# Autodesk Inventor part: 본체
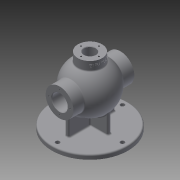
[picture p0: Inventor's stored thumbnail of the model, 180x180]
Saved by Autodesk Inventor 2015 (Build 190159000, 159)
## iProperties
Created: 2020-08
Part Number: 본체
Material: 일반
Document SubType Name: Modeling
Designer: now
Density: 1 g/cm^3
Appearance: 기본값
Author: now
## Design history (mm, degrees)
sketch "스케치1"
  geometry: C1 r 85 at (0, 0); 1 further point
  constraints: 1 centre point, 1 coincident
  dimensions: "d0" = 170 diameter of C1
extrude "돌출1" new body sketch "스케치1" distance "d1" = 10; taper "d2" = 0 deg
sketch "스케치2"
  geometry: L1 (4, 52)-(-4, 52); L2 (-4, 52)-(-4, -52); L3 (-4, -52)-(4, -52); L4 (4, -52)-(4, 52); L5 (4, 52)-(-4, -52); L6 (-4, 52)-(4, -52); C1 r 85 at (0, 0) reference
  constraints: 12 end point, 2 midpoint, 2 parallel, 1 horizontal, 1 perpendicular
  dimensions: "d3" = 104 distance of L3.end L1.start; "d4" = 8 distance of L2.end L3.end
extrude "돌출2" join sketch "스케치2" distance "d5" = 75; taper "d6" = 0 deg
sketch "스케치3"
  geometry: L1 (43, 4)-(-43, 4); L2 (-43, 4)-(-43, -4); L3 (-43, -4)-(43, -4); L4 (43, -4)-(43, 4); L5 (43, 4)-(-43, -4); L6 (-43, 4)-(43, -4); C1 r 85 at (0, 0) reference
  constraints: 12 end point, 2 midpoint, 2 parallel, 1 horizontal, 1 perpendicular
  dimensions: "d7" = 8 distance of L1.end L2.end; "d8" = 86 distance of L2.end L3.end
extrude "돌출3" join sketch "스케치3" distance "d9" = 75; taper "d10" = 0 deg
sketch "스케치4"
  geometry: L1 (85, 10)-(85, 0) reference; L2 (85, 0)-(-85, 0) reference; L3 (-85, 0)-(-85, 10) reference; L4 (-85, 10)-(-52, 10) reference; L5 (-52, 10)-(-52, 85) reference; L6 (-52, 85)-(52, 85) reference; L7 (52, 85)-(52, 10) reference; L8 (52, 10)-(85, 10) reference; L9 (68, 116)-(68, 85); L10 (68, 85)-(-68, 85); L11 (-68, 85)-(-68, 116); L12 (-68, 116)-(-42.988, 116); L13 (42.988, 116)-(68, 116); A1 r 53 centre (0, 85) between (42.988, 116) and (-42.988, 116); 2 further points
  constraints: 10 end point, 3 parallel, 2 horizontal, 2 midpoint, 2 perpendicular, 2 point on circle, 1 centre point, 1 vertical alignment
  dimensions: "d12" = 31 distance of L10.end L11.end; "d13" = 53 radius of A1; "d14" = 136 distance of L11.end L9.start; "d17" = 85 distance of point (0, 0) A1.centre; "d18" = 31 distance between parallel lines of L10 L13
revolve "회전1" sketch "스케치4" stored, may be unused: angle "d19" = 90 deg
node "작업 평면1"
sketch "스케치5"
  geometry: C1 r 27 at (0, 0); 1 further point
  constraints: 1 centre point, 1 coincident
  dimensions: "d21" = 54 diameter of C1
extrude "돌출4" join sketch "스케치5" stored distance "d22" = 75; taper "d23" = 0 deg
sketch "스케치6"
  geometry: L1 (68, 54)-(52, 54) reference; L2 (52, 54)-(52, 10) reference; L3 (52, 10)-(85, 10) reference; L4 (85, 10)-(85, 0) reference; L5 (85, 0)-(-85, 0) reference; L6 (-85, 0)-(-85, 10) reference; L7 (-85, 10)-(-52, 10) reference; L8 (-52, 10)-(-52, 54) reference; L9 (-52, 54)-(-68, 54) reference; L10 (-68, 54)-(-68, 116) reference; L11 (-68, 116)-(-42.988, 116) reference; L12 (-27, 130.607)-(-27, 150) reference; L13 (-27, 150)-(27, 150) reference; L14 (27, 150)-(27, 130.607) reference; L15 (42.988, 116)-(68, 116) reference; L16 (68, 116)-(68, 54) reference; L17 (-68, 54)-(-68, 116) reference; L18 (-68, 85)-(68, 85); L19 (68, 54)-(68, 116) reference; L20 (-43, 85)-(43, 85); L21 (42.988, 54.259)-(42.988, 116) reference; A1 r 53 centre (0, 85) between (-27, 130.607) and (-42.988, 116) reference; A2 r 53 centre (0, 85) between (42.988, 116) and (27, 130.607) reference; A3 r 43 centre (0, 85) between (43, 85) and (-43, 85); 1 further point
  constraints: 4 end point, 2 midpoint, 2 point on circle, 2 point on line, 1 centre point, 1 coincident, 1 perpendicular
  dimensions: "d25" = 43 radius of A3
revolve "회전2" sketch "스케치6" stored, may be unused: angle "d26" = 90 deg
sketch "스케치7"
  geometry: C1 r 31 at (0, 0) reference; C2 r 17.5 at (0, 0); 1 further point
  constraints: 1 centre point, 1 coincident
  dimensions: "d27" = 35 diameter of C2
extrude "돌출5" cut sketch "스케치7" distance "d28" = 16; taper "d29" = 0 deg
sketch "스케치9"
  geometry: C1 r 31 at (0, 0) reference; 1 further point
hole "구멍1" sketch "스케치9" at (0, 0) diameter "d33" = 35; stored, may be unused: countersink angle "d37" = 90 deg, drill point angle "d39" = 118 deg; dims "d34" = 6, "d35" = 4, "d36" = 2, "d38" = 8
sketch "스케치10"
  geometry: C1 r 27 at (0, 0) reference; C2 r 13 at (0, 0)
  constraints: 1 centre point, 1 coincident
  dimensions: "d40" = 26 diameter of C2
extrude "돌출7" cut sketch "스케치10" stored distance "d41" = 1.75; taper "d42" = 0 deg
sketch "스케치11"
  geometry: C1 r 17.5 at (0, 0) reference; 2 further points
  constraints: 1 vertical alignment
  dimensions: "d43" = 24 distance of C1.centre point (0, 24)
hole "구멍2" sketch "스케치11" at (0, 24) diameter "d44" = 3.242; stored, may be unused: countersink angle "d48" = 90 deg, drill point angle "d50" = 118 deg; dims "d45" = 12, "d46" = 4, "d47" = 2, "d49" = 15
sketch "스케치12"
  geometry: C1 r 13 at (0, 0) reference; 1 further point
  constraints: 1 horizontal alignment
  dimensions: "d54" = 20 distance of C1.centre point (-20, 0)
hole "구멍3" sketch "스케치12" at (-20, 0) diameter "d55" = 3.242; stored, may be unused: countersink angle "d59" = 90 deg, drill point angle "d61" = 118 deg; dims "d56" = 12, "d57" = 4, "d58" = 2, "d60" = 15
sketch "스케치13"
  geometry: C1 r 85 at (0, 0) reference; A1 r 72.5 centre (0, 0) between (-72.5, 0) and (0, 72.5); 2 further points
  constraints: 4 point on circle, 2 horizontal alignment, 2 vertical alignment, 1 centre point, 1 coincident
  dimensions: "d65" = 145 diameter of A1
hole "구멍4" sketch "스케치13" at (-72.5, 0), (0, 72.5), (0, -72.5), (72.5, 0) diameter "d66" = 9; stored, may be unused: countersink angle "d70" = 90 deg, drill point angle "d72" = 118 deg; dims "d67" = 12, "d68" = 4, "d69" = 2, "d71" = 15
chamfer "모따기1" distance "d73" = 1; stored, may be unused: second distance "d74" = 2, angle "d75" = 45 deg
chamfer "모따기2" distance "d76" = 1; stored, may be unused: second distance "d77" = 2, angle "d78" = 45 deg
chamfer "모따기3" distance "d79" = 1; stored, may be unused: second distance "d80" = 2, angle "d81" = 45 deg
fillet "모깎기1" dims "d82" = 3
fillet "모깎기2" dims "d83" = 3
fillet "모깎기3" dims "d84" = 3
fillet "모깎기4" dims "d85" = 3
fillet "모깎기5" dims "d86" = 3
fillet "모깎기6" dims "d87" = 3
node "작업 평면2"
sketch "스케치14"
  geometry: L1 (68, 100.232)-(68, 69.768) reference; L2 (68, 69.768)-(44.497, 69.768) reference; L3 (4, 36.441)-(4, 13) reference; L4 (7, 10)-(77.427, 10) reference; L5 (80.598, 7)-(80.598, 0) reference; L6 (80.598, 0)-(-80.598, 0) reference; L7 (-80.598, 0)-(-80.598, 7) reference; L8 (-77.427, 10)-(-7, 10) reference; L9 (-4, 13)-(-4, 36.441) reference; L10 (-44.497, 69.768)-(-68, 69.768) reference; L11 (-68, 69.768)-(-68, 100.232) reference; L12 (-68, 100.232)-(-44.497, 100.232) reference; L13 (44.497, 100.232)-(68, 100.232) reference; L14 (0, 150)-(0, 132.286) reference; L15 (27, 150)-(-27, 150) reference; L16 (27, 150)-(-27, 150) reference; L17 (-27, 132.286)-(27, 132.286) reference; C1 r 33.466 at (0, 85) reference; A1 r 45.607 centre (0, 85) between (6.625, 39.877) and (42.113, 67.494) reference; A2 r 3 centre (7, 13) between (4, 13) and (7, 10) reference; A3 r 3 centre (-7, 13) between (-7, 10) and (-4, 13) reference; A4 r 45.607 centre (0, 85) between (-42.113, 67.494) and (-6.625, 39.877) reference; A5 r 45.607 centre (0, 85) between (-8.784, 129.753) and (-42.113, 102.506) reference; A6 r 45.607 centre (0, 85) between (42.113, 102.506) and (8.784, 129.753) reference; 2 further points
  constraints: 11 other
  dimensions: "d89" = 27 horizontal distance of L15.end point (0, 141); "d90" = 9 vertical distance of L15.end point (0, 141)
feature "엠보싱1" sketch "스케치14" dims "d7" = 8, "d8" = 86, "d91" = 0.5, "d92" = 0
node "작업 평면3"
sketch "스케치15"
  geometry: L1 (-6.196, 75)-(-63.403, 75) reference; L2 (-67.238, 78)-(-67.238, 85) reference; L3 (-67.238, 85)-(67.238, 85) reference; L4 (67.238, 85)-(67.238, 78) reference; L5 (63.403, 75)-(6.196, 75) reference; L6 (1, 72)-(-1, 72) reference; L7 (-1, 72)-(-1, 33.985) reference; L8 (1, 72)-(1, 33.985) reference; C1 r 17.5 at (0, 0) reference; C2 r 18.5 at (0, 0); A1 r 31 centre (0, 0) between (-5.649, 30.481) and (5.649, 30.481) reference; A2 r 34 centre (0, 0) between (1, 33.985) and (-1, 33.985) reference; 1 further point
  constraints: 1 centre point, 1 coincident, 6 other
  dimensions: "d94" = 37 diameter of C2
extrude "돌출8" cut sketch "스케치15" distance "d95" = 1.75; taper "d96" = 0 deg
node "솔리드1"
pattern_circular "원형 패턴1" dims angle "d52" = 360 deg
mirror "대칭1"
pattern_circular "원형 패턴2" dims angle "d63" = 360 deg
node "투영된 루프1"
node "절단 모서리 투영1"
node "절단 모서리 투영2"
node "절단 모서리 투영3"
node "절단 모서리 투영4"
other parameters: "d88" = 27, "d93" = -16
